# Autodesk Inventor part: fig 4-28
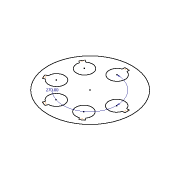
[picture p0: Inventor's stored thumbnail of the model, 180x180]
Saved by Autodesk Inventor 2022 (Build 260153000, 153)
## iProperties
Created: 2004-05
Part Number: fig 4-28
Document SubType Name: Modeling
Designer: CADCIM Technologies
Manufacturer: Standard
Standards Organization: Custom
Density: 1 g/cm^3
Material: Generic
Appearance: Default
Author: CADCIM Technologies
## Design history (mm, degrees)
sketch "Sketch2"
  geometry: L1 (0.73, 11.049)-(0.73, 11.828); L2 (0.73, 11.828)-(-0.73, 11.828); L3 (-0.73, 11.828)-(-0.73, 11.006); L4 (-0.152, 11.061)-(0.73, 11.828); L5 (0.152, 11.061)-(-0.73, 11.828); L6 (-8.51, 7.085)-(-9.14, 7.543); L7 (-9.14, 7.543)-(-9.998, 6.362); L8 (-9.998, 6.362)-(-9.333, 5.879); L9 (-9.038, 6.378)-(-9.14, 7.543); L10 (-8.859, 6.625)-(-9.998, 6.362); L11 (-10.734, -2.72)-(-11.474, -2.961); L12 (-11.474, -2.961)-(-11.023, -4.349); L13 (-11.023, -4.349)-(-10.242, -4.095); L14 (-10.472, -3.563)-(-11.474, -2.961); L15 (-10.566, -3.273)-(-11.023, -4.349); L16 (-4.108, -10.283)-(-4.349, -11.023); L17 (-4.349, -11.023)-(-2.961, -11.474); L18 (-2.961, -11.474)-(-2.707, -10.693); L19 (-3.273, -10.566)-(-4.349, -11.023); L20 (-3.563, -10.472)-(-2.961, -11.474); L21 (5.904, -9.368)-(6.362, -9.998); L22 (6.362, -9.998)-(7.543, -9.14); L23 (7.543, -9.14)-(7.06, -8.475); L24 (6.625, -8.859)-(6.362, -9.998); L25 (6.378, -9.038)-(7.543, -9.14); L26 (11.049, -0.73)-(11.828, -0.73); L27 (11.828, -0.73)-(11.828, 0.73); L28 (11.828, 0.73)-(11.006, 0.73); L29 (11.061, 0.152)-(11.828, -0.73); L30 (11.061, -0.152)-(11.828, 0.73); C1 r 13.473 at (0, 0); A1 r 2.558 centre (0.072, 8.577) between (-0.73, 11.006) and (0.73, 11.049); A2 r 2.558 centre (-6.897, 5.1) between (-9.333, 5.879) and (-8.51, 7.085); A3 r 2.558 centre (-8.18, -2.582) between (-10.242, -4.095) and (-10.734, -2.72); A4 r 2.558 centre (-2.719, -8.135) between (-2.707, -10.693) and (-4.108, -10.283); A5 r 2.558 centre (4.983, -6.981) between (7.06, -8.475) and (5.904, -9.368); A6 r 2.558 centre (8.577, -0.072) between (11.006, 0.73) and (11.049, -0.73); 6 further points
  constraints: 60 end point, 12 point on circle, 7 centre point, 2 coincident, 1 parallel, 70 other
  dimensions: "d6" = 270 deg dimension on point (0, 0) A1.centre A6.centre
